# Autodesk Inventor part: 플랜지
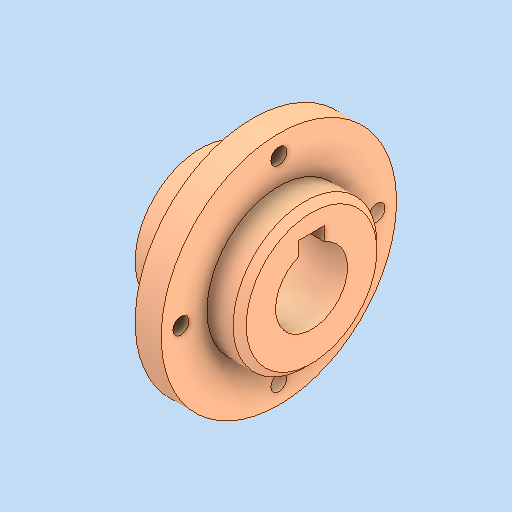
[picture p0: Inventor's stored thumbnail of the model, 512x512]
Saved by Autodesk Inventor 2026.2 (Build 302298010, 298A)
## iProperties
Created: 2026-08
Part Number: 플랜지
Material: 스테인리스강
Document SubType Name: Modeling
Designer: PC2-02
Density: 8.08 g/cm^3
Appearance: 기본값
Author: jhkim
Sending System: Autodesk Inventor 2027
Preprocessor: ST-DEVELOPER v20.1
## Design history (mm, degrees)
feature "솔리드1"
node "솔리드2"
